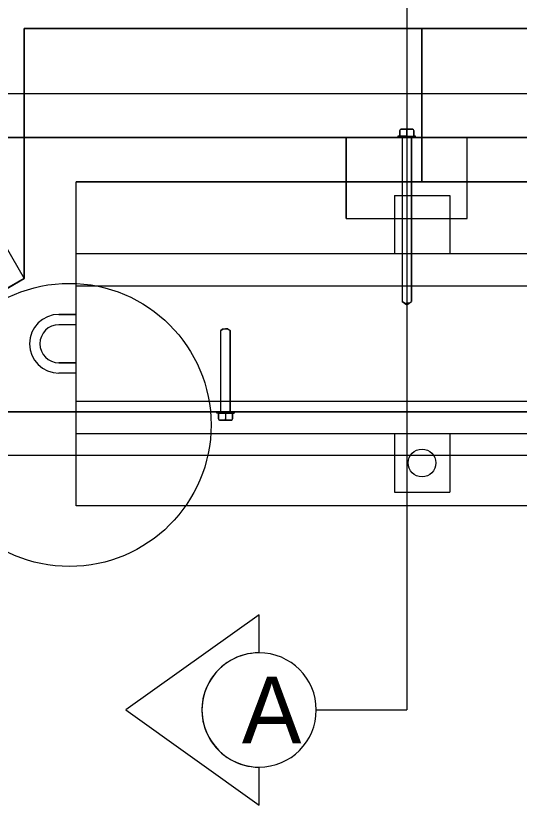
# Model space of a CAD drawing. Extents: x 10028 to 81668, y 3581 to 11018.
# Drawn here: x 17755.7 to 17870.2, y 8654.3 to 8833.9 of the extents above; entities that cross this region are included whole.
import ezdxf

# ---------------------------------------------------------------- set-up
doc = ezdxf.new("R2010")
doc.units = 0
for name, color, linetype in [('conPaving', 7, 'Continuous'), ('dsnCellsNorthArrow', 7, 'Continuous'), ('dsnTextTabulation', 7, 'Continuous'), ('Level 41', 7, 'Continuous'), ('Level 9', 7, 'Continuous')]:
    doc.layers.add(name, color=color, linetype=linetype)

msp = doc.modelspace()

# ---------------------------------------------------------------- linework, layer by layer
at = {"layer": 'conPaving'}
for p, q in [((17987.17, 8816.12), (17702.09, 8816.12)), ((17843.04, 8807.76), (17843.04, 8806.5)), ((17844.92, 8808.08), (17843.32, 8808.08)), ((17845.94, 8808.08), (17844.92, 8808.08)), ((17846.22, 8806.5), (17846.22, 8807.76)), ((17681.03, 8806.21), (18008.23, 8806.21)), ((17843.04, 8806.5), (17842.64, 8806.5)), ((17842.64, 8806.5), (17842.64, 8806.21)), ((17842.64, 8806.21), (17843.57, 8806.21)), ((17843.57, 8806.21), (17843.57, 8768.92)), ((17845.69, 8768.92), (17845.69, 8806.21)), ((17845.69, 8806.21), (17846.62, 8806.21)), ((17846.62, 8806.5), (17846.22, 8806.5)), ((17846.62, 8806.21), (17846.62, 8806.5)), ((17843.57, 8768.92), (17844.64, 8768.15)), ((17844.64, 8768.16), (17845.69, 8768.92)), ((17844.64, 8768.15), (17844.64, 8768.17)), ((17844.64, 8768.17), (17844.64, 8768.16)), ((17765.53, 8765.96), (17769.47, 8765.96)), ((17802.37, 8762.26), (17802.9, 8762.65)), ((17802.37, 8743.77), (17802.37, 8762.26)), ((17802.9, 8762.65), (17803.43, 8762.65)), ((17803.43, 8762.65), (17803.96, 8762.65)), ((17803.96, 8762.65), (17804.49, 8762.26)), ((17804.49, 8762.26), (17804.49, 8743.77)), ((17769.47, 8752.59), (17765.53, 8752.59)), ((17640.31, 8743.77), (17967.51, 8743.77)), ((17801.44, 8743.48), (17801.44, 8743.77)), ((17801.44, 8743.77), (17802.37, 8743.77)), ((17801.84, 8743.48), (17801.44, 8743.48)), ((17801.84, 8742.22), (17801.84, 8743.48)), ((17804.49, 8743.77), (17805.42, 8743.77)), ((17805.42, 8743.48), (17805.02, 8743.48)), ((17805.02, 8743.48), (17805.02, 8742.22)), ((17805.42, 8743.77), (17805.42, 8743.48)), ((17803.71, 8741.91), (17802.12, 8741.91)), ((17804.74, 8741.91), (17803.71, 8741.91)), ((17946.45, 8733.87), (17661.37, 8733.87))]:
    msp.add_line(p, q, dxfattribs=at)
for points in [[(17769.47, 8765.96), (17769.47, 8796.14), (17848.05, 8796.14), (17848.05, 8831.02), (17757.59, 8831.02), (17757.63, 8774.09)], [(17757.63, 8774.09), (17705.12, 8743.77), (17769.47, 8743.77), (17769.47, 8752.59)]]:
    msp.add_lwpolyline(points, dxfattribs=at)
msp.add_arc((17765.53, 8759.28), 6.68, 90, 270, dxfattribs=at)
for centre, major_axis, start_param, end_param in [((17843.32, 8807.76), (0, 0.315), 0, 1.570796), ((17845.94, 8807.76), (0, 0.315), 4.712389, 6.283185), ((17802.12, 8742.22), (0, -0.315), 4.712389, 6.283185), ((17804.74, 8742.22), (0, -0.315), 6.283185, 7.853982)]:
    msp.add_ellipse(centre, major_axis=major_axis, ratio=0.899999, start_param=start_param, end_param=end_param, dxfattribs=at)
at = {"layer": 'dsnCellsNorthArrow'}
for p, q in [((17811.05, 8697.64), (17780.72, 8675.97)), ((17811.05, 8688.97), (17811.05, 8697.64)), ((17780.72, 8675.97), (17811.05, 8654.31)), ((17811.05, 8654.31), (17811.05, 8662.97))]:
    msp.add_line(p, q, dxfattribs=at)
for centre, start, end in [((17811.05, 8675.97), 89.9948, 270.0052), ((17811.06, 8675.97), 90.0052, 269.9948), ((17811.05, 8675.97), 270.0052, 89.9948)]:
    msp.add_arc(centre, 13, start, end, dxfattribs=at)
at = {"layer": 'dsnTextTabulation'}
for p, q in [((17844.62, 8865.12), (17844.62, 8675.97)), ((17739.82, 8804.94), (17757.63, 8774.09)), ((18260.99, 8796.14), (17769.47, 8796.14)), ((17769.47, 8722.41), (17769.47, 8796.14)), ((18260.99, 8779.76), (17769.47, 8779.76)), ((17696.58, 8738.84), (17757.63, 8774.09)), ((18260.99, 8772.38), (17769.47, 8772.38)), ((18260.99, 8746.17), (17769.47, 8746.17)), ((18260.99, 8738.8), (17769.47, 8738.8)), ((18260.99, 8722.41), (17769.47, 8722.41)), ((17824.05, 8675.97), (17844.62, 8675.97))]:
    msp.add_line(p, q, dxfattribs=at)
at = {"layer": 'Level 41'}
for p, q in [((17841.82, 8793.02), (17854.4, 8793.02)), ((17841.82, 8793.02), (17841.82, 8779.76)), ((17854.4, 8793.02), (17854.4, 8779.76)), ((17769.47, 8765.96), (17765.53, 8765.96)), ((17769.47, 8763.6), (17765.53, 8763.6)), ((17769.47, 8754.95), (17765.53, 8754.95)), ((17769.47, 8752.59), (17765.53, 8752.59)), ((17841.82, 8738.8), (17841.82, 8725.54)), ((17854.4, 8738.8), (17854.4, 8725.54)), ((17841.82, 8725.54), (17854.4, 8725.54))]:
    msp.add_line(p, q, dxfattribs=at)
msp.add_circle((17848.11, 8732.17), 3.15, dxfattribs=at)
for radius in [6.68, 4.33]:
    msp.add_arc((17765.53, 8759.28), radius, 90, 270, dxfattribs=at)
at = {"layer": 'Level 9'}
for p, q in [((17757.59, 8774.17), (17757.59, 8831.02)), ((17757.59, 8831.02), (19777.13, 8831.02)), ((18257.99, 8831.02), (17848.05, 8831.02)), ((17848.05, 8831.02), (17848.05, 8796.14)), ((17987.17, 8816.12), (17702.09, 8816.12)), ((17843.04, 8806.5), (17843.04, 8807.76)), ((17843.32, 8808.08), (17844.35, 8808.08)), ((17844.35, 8808.08), (17845.94, 8808.08)), ((17844.63, 8806.5), (17844.63, 8807.76)), ((17846.22, 8807.76), (17846.22, 8806.5)), ((18042.06, 8806.21), (17647.2, 8806.21)), ((17830.87, 8806.21), (17830.87, 8787.81)), ((17858.39, 8806.21), (17830.87, 8806.21)), ((17830.87, 8787.81), (17830.87, 8806.21)), ((17844.63, 8806.5), (17842.64, 8806.5)), ((17842.64, 8806.5), (17842.64, 8806.21)), ((17842.64, 8806.21), (17846.62, 8806.21)), ((17843.04, 8806.5), (17846.22, 8806.5)), ((17843.57, 8806.21), (17843.57, 8768.92)), ((17844.63, 8806.5), (17846.62, 8806.5)), ((17844.63, 8806.21), (17845.69, 8806.21)), ((17845.69, 8806.21), (17845.69, 8787.81)), ((17845.69, 8806.21), (17845.69, 8768.92)), ((17846.62, 8806.21), (17846.62, 8806.5)), ((17858.39, 8787.81), (17858.39, 8806.21)), ((17858.39, 8787.81), (17858.39, 8806.21)), ((17848.05, 8796.14), (18260.99, 8796.14)), ((17830.87, 8787.81), (17858.39, 8787.81)), ((17830.87, 8787.81), (17858.39, 8787.81)), ((17844.1, 8768.54), (17843.57, 8768.92)), ((17844.1, 8768.54), (17844.63, 8768.54)), ((17845.16, 8768.54), (17844.63, 8768.54)), ((17845.16, 8768.54), (17845.69, 8768.92)), ((17769.47, 8763.6), (17765.53, 8763.6)), ((17769.47, 8754.95), (17769.47, 8763.6)), ((17802.9, 8762.65), (17802.37, 8762.26)), ((17802.37, 8743.77), (17802.37, 8762.26)), ((17802.9, 8762.65), (17803.43, 8762.65)), ((17803.96, 8762.65), (17803.43, 8762.65)), ((17803.96, 8762.65), (17804.49, 8762.26)), ((17804.49, 8743.77), (17804.49, 8762.26)), ((17765.53, 8754.95), (17769.47, 8754.95)), ((18001.34, 8743.77), (17606.48, 8743.77)), ((17801.44, 8743.48), (17801.44, 8743.77)), ((17801.44, 8743.77), (17805.42, 8743.77)), ((17803.43, 8743.48), (17801.44, 8743.48)), ((17801.84, 8743.48), (17805.02, 8743.48)), ((17801.84, 8743.48), (17801.84, 8742.22)), ((17803.43, 8743.77), (17804.49, 8743.77)), ((17803.43, 8743.48), (17805.42, 8743.48)), ((17803.43, 8743.48), (17803.43, 8742.22)), ((17805.02, 8742.22), (17805.02, 8743.48)), ((17805.42, 8743.77), (17805.42, 8743.48)), ((17802.12, 8741.91), (17803.15, 8741.91)), ((17803.15, 8741.91), (17804.74, 8741.91)), ((17946.45, 8733.87), (17661.37, 8733.87))]:
    msp.add_line(p, q, dxfattribs=at)
msp.add_circle((17767.93, 8740.82), 32.2, dxfattribs=at)
msp.add_arc((17765.53, 8759.28), 4.33, 90, 270, dxfattribs=at)
for centre, start_param, end_param in [((17843.32, 8807.76), 6.283185, 7.853982), ((17844.35, 8807.76), 4.712389, 6.283185), ((17844.92, 8807.76), 0, 1.570796), ((17845.94, 8807.76), 4.712389, 6.283185), ((17802.12, 8742.22), 1.570796, 3.141593), ((17803.15, 8742.22), 3.141593, 4.712389), ((17803.71, 8742.22), 1.570796, 3.141593), ((17804.74, 8742.22), 3.141593, 4.712389)]:
    msp.add_ellipse(centre, major_axis=(0, 0.315), ratio=0.899999, start_param=start_param, end_param=end_param, dxfattribs=at)

# ---------------------------------------------------------------- texts
at = {"layer": 'dsnCellsNorthArrow'}
msp.add_text('A', height=15.2, dxfattribs=at).set_placement((17807.13, 8668.37))

doc.saveas('drawing.dxf')
